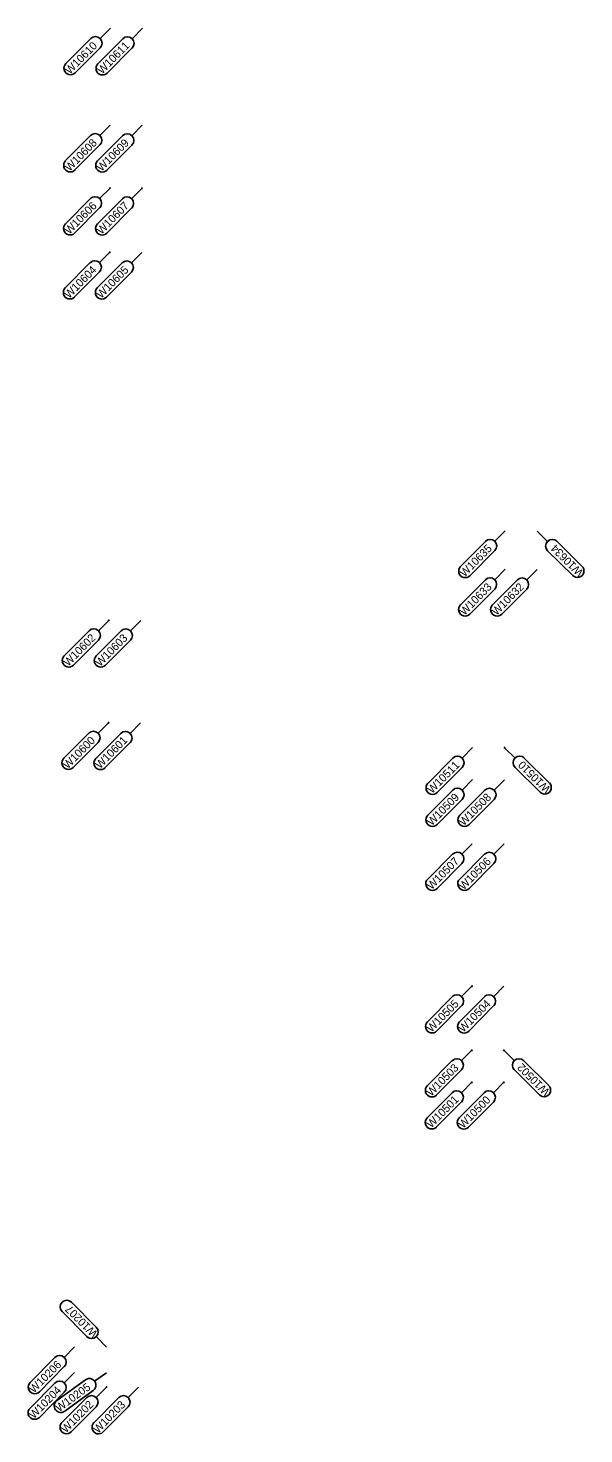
# Model space of a CAD drawing. Extents: x 12479652 to 12487250, y 9842710 to 9846560.
# Drawn here: x 12483668.3 to 12483755.1, y 9845390.1 to 9845609.6 of the extents above; entities that cross this region are included whole.
import ezdxf

# ---------------------------------------------------------------- set-up
doc = ezdxf.new("R2010")
doc.units = 0
doc.layers.add('Default', color=7, linetype='Continuous')
doc.layers.add('TextAlignmentLrg', color=7, linetype='Continuous')

msp = doc.modelspace()

# ---------------------------------------------------------------- linework, layer by layer
at = {"layer": 'Default'}
for p, q in [((12483681.16, 9845609.64), (12483679.54, 9845608.01)), ((12483686.16, 9845609.62), (12483684.54, 9845607.99)), ((12483674.2, 9845604.09), (12483678.09, 9845608.01)), ((12483679.55, 9845606.56), (12483675.66, 9845602.65)), ((12483679.2, 9845604.07), (12483683.09, 9845607.99)), ((12483684.55, 9845606.54), (12483680.66, 9845602.63)), ((12483681.12, 9845594.48), (12483679.5, 9845592.85)), ((12483686.12, 9845594.46), (12483684.5, 9845592.83)), ((12483674.16, 9845588.94), (12483678.05, 9845592.85)), ((12483679.5, 9845591.4), (12483675.61, 9845587.49)), ((12483679.16, 9845588.91), (12483683.05, 9845592.83)), ((12483684.5, 9845591.38), (12483680.61, 9845587.47)), ((12483681.09, 9845584.64), (12483679.47, 9845583.01)), ((12483686.09, 9845584.62), (12483684.47, 9845582.99)), ((12483674.13, 9845579.1), (12483678.02, 9845583.01)), ((12483679.13, 9845579.07), (12483683.02, 9845582.99)), ((12483679.47, 9845581.56), (12483675.59, 9845577.65)), ((12483684.47, 9845581.54), (12483680.58, 9845577.63)), ((12483681.06, 9845574.64), (12483679.44, 9845573.01)), ((12483686.06, 9845574.62), (12483684.44, 9845572.99)), ((12483674.1, 9845569.1), (12483677.99, 9845573.01)), ((12483679.45, 9845571.56), (12483675.56, 9845567.65)), ((12483679.1, 9845569.07), (12483682.99, 9845572.99)), ((12483684.45, 9845571.54), (12483680.56, 9845567.63)), ((12483735.86, 9845525.57), (12483739.75, 9845529.48)), ((12483742.83, 9845531.12), (12483741.2, 9845529.49)), ((12483747.83, 9845531.1), (12483749.46, 9845529.48)), ((12483750.91, 9845529.49), (12483754.82, 9845525.6)), ((12483741.21, 9845528.04), (12483737.32, 9845524.12)), ((12483753.37, 9845524.14), (12483749.46, 9845528.03)), ((12483742.81, 9845525.12), (12483741.19, 9845523.49)), ((12483747.81, 9845525.1), (12483746.19, 9845523.47)), ((12483735.85, 9845519.57), (12483739.74, 9845523.48)), ((12483740.85, 9845519.55), (12483744.74, 9845523.47)), ((12483741.19, 9845522.04), (12483737.3, 9845518.12)), ((12483746.19, 9845522.02), (12483742.3, 9845518.11)), ((12483680.9, 9845517.15), (12483679.27, 9845515.52)), ((12483685.9, 9845517.13), (12483684.27, 9845515.5)), ((12483673.93, 9845511.61), (12483677.82, 9845515.52)), ((12483679.28, 9845514.07), (12483675.39, 9845510.16)), ((12483678.93, 9845511.58), (12483682.82, 9845515.5)), ((12483684.28, 9845514.05), (12483680.39, 9845510.14)), ((12483680.85, 9845501.15), (12483679.23, 9845499.52)), ((12483685.85, 9845501.13), (12483684.23, 9845499.5)), ((12483673.89, 9845495.61), (12483677.78, 9845499.52)), ((12483678.89, 9845495.58), (12483682.78, 9845499.5)), ((12483679.23, 9845498.07), (12483675.34, 9845494.16)), ((12483684.23, 9845498.05), (12483680.34, 9845494.14)), ((12483737.73, 9845497.27), (12483736.11, 9845495.64)), ((12483742.73, 9845497.26), (12483744.36, 9845495.64)), ((12483730.77, 9845491.72), (12483734.66, 9845495.63)), ((12483745.81, 9845495.64), (12483749.72, 9845491.75)), ((12483736.11, 9845494.19), (12483732.22, 9845490.27)), ((12483737.71, 9845492.27), (12483736.09, 9845490.64)), ((12483742.71, 9845492.26), (12483741.09, 9845490.63)), ((12483748.28, 9845490.3), (12483744.36, 9845494.19)), ((12483730.75, 9845486.72), (12483734.64, 9845490.63)), ((12483735.75, 9845486.71), (12483739.64, 9845490.62)), ((12483736.1, 9845489.19), (12483732.21, 9845485.27)), ((12483741.1, 9845489.18), (12483737.21, 9845485.27)), ((12483737.69, 9845482.27), (12483736.06, 9845480.64)), ((12483742.69, 9845482.26), (12483741.06, 9845480.63)), ((12483730.72, 9845476.72), (12483734.61, 9845480.64)), ((12483736.07, 9845479.19), (12483732.18, 9845475.28)), ((12483735.72, 9845476.71), (12483739.61, 9845480.62)), ((12483741.07, 9845479.18), (12483737.18, 9845475.27)), ((12483737.64, 9845460.01), (12483736.02, 9845458.38)), ((12483742.64, 9845460.01), (12483741.02, 9845458.37)), ((12483730.68, 9845454.46), (12483734.57, 9845458.38)), ((12483735.68, 9845454.46), (12483739.57, 9845458.37)), ((12483736.02, 9845456.93), (12483732.13, 9845453.02)), ((12483741.02, 9845456.92), (12483737.13, 9845453.01)), ((12483730.66, 9845444.46), (12483734.55, 9845448.38)), ((12483737.62, 9845450.01), (12483736, 9845448.38)), ((12483742.62, 9845450.01), (12483744.25, 9845448.38)), ((12483745.7, 9845448.39), (12483749.62, 9845444.5)), ((12483736, 9845446.93), (12483732.11, 9845443.02)), ((12483748.17, 9845443.04), (12483744.26, 9845446.93)), ((12483737.61, 9845445.01), (12483735.99, 9845443.38)), ((12483742.61, 9845445.01), (12483740.99, 9845443.37)), ((12483730.65, 9845439.46), (12483734.54, 9845443.38)), ((12483735.99, 9845441.93), (12483732.1, 9845438.02)), ((12483735.65, 9845439.46), (12483739.54, 9845443.37)), ((12483740.99, 9845441.92), (12483737.1, 9845438.01)), ((12483673.6, 9845409.2), (12483677.49, 9845405.29)), ((12483678.95, 9845406.74), (12483675.06, 9845410.65)), ((12483680.56, 9845403.65), (12483678.94, 9845405.28)), ((12483675.56, 9845403.67), (12483673.94, 9845402.04)), ((12483668.6, 9845398.12), (12483672.49, 9845402.03)), ((12483673.95, 9845400.59), (12483670.06, 9845396.67)), ((12483668.59, 9845394.12), (12483672.48, 9845398.03)), ((12483672.8, 9845395.28), (12483677.26, 9845398.53)), ((12483675.55, 9845399.67), (12483673.93, 9845398.04)), ((12483680.55, 9845399.65), (12483678.69, 9845398.3)), ((12483673.94, 9845396.59), (12483670.05, 9845392.67)), ((12483673.58, 9845391.86), (12483677.47, 9845395.77)), ((12483678.47, 9845396.87), (12483674.01, 9845393.62)), ((12483678.58, 9845391.84), (12483682.47, 9845395.75)), ((12483680.55, 9845397.41), (12483678.92, 9845395.78)), ((12483685.55, 9845397.39), (12483683.92, 9845395.76)), ((12483678.93, 9845394.33), (12483675.04, 9845390.42)), ((12483683.93, 9845394.31), (12483680.04, 9845390.39))]:
    msp.add_line(p, q, dxfattribs=at)
for centre, start, end in [((12483678.82, 9845607.28), 315.1702, 135.1702), ((12483683.82, 9845607.26), 315.1702, 135.1702), ((12483674.93, 9845603.37), 135.1702, 315.1702), ((12483679.93, 9845603.35), 135.1702, 315.1702), ((12483678.78, 9845592.13), 315.1702, 135.1702), ((12483683.78, 9845592.1), 315.1702, 135.1702), ((12483674.89, 9845588.21), 135.1702, 315.1702), ((12483679.89, 9845588.19), 135.1702, 315.1702), ((12483678.75, 9845582.28), 315.1702, 135.1702), ((12483683.75, 9845582.26), 315.1702, 135.1702), ((12483674.86, 9845578.37), 135.1702, 315.1702), ((12483679.86, 9845578.35), 135.1702, 315.1702), ((12483678.72, 9845572.28), 315.1702, 135.1702), ((12483683.72, 9845572.26), 315.1702, 135.1702), ((12483674.83, 9845568.37), 135.1702, 315.1702), ((12483679.83, 9845568.35), 135.1702, 315.1702), ((12483740.48, 9845528.76), 315.1702, 135.1702), ((12483750.18, 9845528.76), 45.1702, 225.1702), ((12483736.59, 9845524.85), 135.1702, 315.1702), ((12483754.1, 9845524.87), 225.1702, 45.1702), ((12483740.46, 9845522.76), 315.1702, 135.1702), ((12483745.46, 9845522.74), 315.1702, 135.1702), ((12483736.57, 9845518.85), 135.1702, 315.1702), ((12483741.57, 9845518.83), 135.1702, 315.1702), ((12483678.55, 9845514.8), 315.1702, 135.1702), ((12483683.55, 9845514.77), 315.1702, 135.1702), ((12483674.66, 9845510.88), 135.1702, 315.1702), ((12483679.66, 9845510.86), 135.1702, 315.1702), ((12483678.5, 9845498.8), 315.1702, 135.1702), ((12483683.5, 9845498.77), 315.1702, 135.1702), ((12483674.61, 9845494.88), 135.1702, 315.1702), ((12483679.61, 9845494.86), 135.1702, 315.1702), ((12483735.38, 9845494.91), 315.1702, 135.1702), ((12483745.09, 9845494.92), 45.1702, 225.1702), ((12483731.49, 9845491), 135.1702, 315.1702), ((12483735.37, 9845489.91), 315.1702, 135.1702), ((12483740.37, 9845489.9), 315.1702, 135.1702), ((12483749, 9845491.03), 225.1702, 45.1702), ((12483731.48, 9845486), 135.1702, 315.1702), ((12483736.48, 9845485.99), 135.1702, 315.1702), ((12483735.34, 9845479.91), 315.1702, 135.1702), ((12483740.34, 9845479.9), 315.1702, 135.1702), ((12483731.45, 9845476), 135.1702, 315.1702), ((12483736.45, 9845475.99), 135.1702, 315.1702), ((12483735.3, 9845457.65), 315.1702, 135.1702), ((12483740.3, 9845457.65), 315.1702, 135.1702), ((12483731.41, 9845453.74), 135.1702, 315.1702), ((12483736.41, 9845453.73), 135.1702, 315.1702), ((12483735.28, 9845447.65), 315.1702, 135.1702), ((12483744.98, 9845447.66), 45.1702, 225.1702), ((12483731.39, 9845443.74), 135.1702, 315.1702), ((12483748.89, 9845443.77), 225.1702, 45.1702), ((12483735.27, 9845442.65), 315.1702, 135.1702), ((12483740.27, 9845442.65), 315.1702, 135.1702), ((12483731.38, 9845438.74), 135.1702, 315.1702), ((12483736.38, 9845438.73), 135.1702, 315.1702), ((12483674.33, 9845409.93), 44.8253, 224.8253), ((12483678.22, 9845406.01), 224.8253, 44.8253), ((12483673.22, 9845401.31), 315.1702, 135.1702), ((12483669.33, 9845397.4), 135.1702, 315.1702), ((12483673.21, 9845397.31), 315.1702, 135.1702), ((12483677.86, 9845397.7), 306.0372, 126.0372), ((12483678.2, 9845395.05), 315.1702, 135.1702), ((12483683.2, 9845395.03), 315.1702, 135.1702), ((12483669.32, 9845393.4), 135.1702, 315.1702), ((12483673.4, 9845394.45), 126.0372, 306.0372), ((12483674.31, 9845391.14), 135.1702, 315.1702), ((12483679.31, 9845391.12), 135.1702, 315.1702)]:
    msp.add_arc(centre, 1.03, start, end, dxfattribs=at)
at = {"layer": 'TextAlignmentLrg'}
for centre in [(12483681.09, 9845584.64), (12483686.09, 9845584.62), (12483681.06, 9845574.64), (12483680.9, 9845517.15), (12483680.85, 9845501.15), (12483742.73, 9845497.26), (12483737.64, 9845460.01), (12483737.62, 9845450.01), (12483742.62, 9845450.01), (12483737.61, 9845445.01), (12483742.61, 9845445.01), (12483680.55, 9845397.41)]:
    msp.add_circle(centre, 0.05, dxfattribs=at)

# ---------------------------------------------------------------- texts
at = {"layer": 'Default'}
for s, rotation, p in [('W10610', 45.1702, (12483674.81, 9845602.35)), ('W10611', 45.1702, (12483679.85, 9845602.37)), ('W10608', 45.1702, (12483674.77, 9845587.19)), ('W10609', 45.1702, (12483679.77, 9845587.17)), ('W10606', 45.1702, (12483674.74, 9845577.35)), ('W10607', 45.1702, (12483679.75, 9845577.34)), ('W10604', 45.1702, (12483674.7, 9845567.34)), ('W10605', 45.1702, (12483679.72, 9845567.34)), ('W10635', 45.1702, (12483736.48, 9845523.84)), ('W10634', 135.1702, (12483755.13, 9845524.74)), ('W10633', 45.1702, (12483736.46, 9845517.83)), ('W10632', 45.1702, (12483741.47, 9845517.83)), ('W10602', 45.1702, (12483674.56, 9845509.88)), ('W10603', 45.1702, (12483679.55, 9845509.85)), ('W10600', 45.1702, (12483674.49, 9845493.86)), ('W10601', 45.1702, (12483679.53, 9845493.88)), ('W10511', 45.1702, (12483731.41, 9845490.01)), ('W10510', 135.1702, (12483750.02, 9845490.91)), ('W10509', 45.1702, (12483731.36, 9845484.98)), ('W10508', 45.1702, (12483736.36, 9845484.97)), ('W10507', 45.1702, (12483731.34, 9845474.99)), ('W10506', 45.1702, (12483736.33, 9845474.96)), ('W10505', 45.1702, (12483731.3, 9845452.73)), ('W10504', 45.1702, (12483736.28, 9845452.71)), ('W10503', 45.1702, (12483731.27, 9845442.73)), ('W10502', 135.1702, (12483749.89, 9845443.67)), ('W10501', 45.1702, (12483731.29, 9845437.76)), ('W10500', 45.1702, (12483736.26, 9845437.71)), ('W10207', 134.8253, (12483679.25, 9845405.88)), ('W10206', 45.1702, (12483669.21, 9845396.37)), ('W10205', 36.0372, (12483673.14, 9845393.47)), ('W10204', 45.1702, (12483669.19, 9845392.37)), ('W10202', 45.1702, (12483674.21, 9845390.14)), ('W10203', 45.1702, (12483679.2, 9845390.1))]:
    msp.add_text(s, height=1.25, rotation=rotation, dxfattribs=at).set_placement(p)

doc.saveas('drawing.dxf')
